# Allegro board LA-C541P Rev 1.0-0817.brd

Outline 356 x 159.9 mm; copper layers: TOP, GND1, IN1, VCC, IN2, IN3, GND2, IN4, GND3, BOTTOM. Coordinates in mm from the lower left corner of the outline.
Outline path: circle c246.25,119.45 r3.5 ; circle c282.95,32.65 r3.5 ; 0,68.4 arc(0.88,70.52) 3,71.4 23.4,71.4 arc(24.11,71.11) 24.4,70.4 24.4,69.4 arc(24.69,68.69) 25.4,68.4 46.5,68.4 arc(47.21,68.69) 47.5,69.4 47.5,70.4 arc(47.79,71.11) 48.5,71.4 52.1,71.4 arc(53.95,71.45) 55.79,71.59 arc(57.34,71.09) 58,69.6 58,69.4 arc(61,66.4) 64,69.4 64,72.03 65.27,73.89 arc(82.27,87.75) 88.07,108.9 arc(88.09,109.65) 88.1,110.4 88.1,123.55 arc(88.25,124.32) 88.69,124.96 95.81,132.09 arc(96.02,132.41) 96.1,132.79 96.1,140.74 arc(96.25,141.51) 96.69,142.16 100.64,146.11 arc(100.96,146.32) 101.34,146.4 102,146.4 arc(102.71,146.69) 103,147.4 arc(103.44,148.46) 104.5,148.9 104.5,157.9 arc(105.09,159.31) 106.5,159.9 117.5,159.9 arc(118.21,159.61) 118.5,158.9 118.5,158.2 arc(118.79,157.49) 119.5,157.2 124.5,157.2 arc(125.21,156.91) 125.5,156.2 125.5,152 arc(132.5,145) 139.5,152 139.5,156.2 arc(139.79,156.91) 140.5,157.2 145.5,157.2 arc(146.21,157.49) 146.5,158.2 146.5,158.9 arc(146.79,159.61) 147.5,159.9 205.5,159.9 arc(206.21,159.61) 206.5,158.9 206.5,158.2 arc(206.79,157.49) 207.5,157.2 212.5,157.2 arc(213.21,156.91) 213.5,156.2 213.5,152 arc(220.5,145) 227.5,152 227.5,156.9 arc(228.09,158.31) 229.5,158.9 230.6,158.9 arc(231.31,158.61) 231.6,157.9 231.6,150.95 arc(231.85,150.7) 232.1,150.95 233.6,150.95 arc(233.81,150.86) 233.9,150.65 233.9,150 arc(233.99,149.79) 234.2,149.7 243.2,149.7 arc(243.41,149.79) 243.5,150 243.5,150.65 arc(243.59,150.86) 243.8,150.95 245.3,150.95 arc(245.55,150.7) 245.8,150.95 245.8,157.9 arc(246.09,158.61) 246.8,158.9 248,158.9 arc(248.71,158.61) 249,157.9 249,152.7 arc(249.29,151.99) 250,151.7 256.8,151.7 arc(257.51,151.41) 257.8,150.7 257.8,136.31 arc(257.89,135.73) 258.14,135.2 259.46,133.2 arc(259.71,132.67) 259.8,132.09 259.8,87 arc(278.6,55.37) 315.37,56.79 318.46,55.11 318.46,51 arc(321.25,49.1) 324.04,51 324.04,59.17 arc(324.19,59.94) 324.63,60.59 328.46,64.41 arc(329.1,64.85) 329.87,65 348,65 arc(349.41,64.41) 350,63 350,51.4 arc(350.29,50.69) 351,50.4 355,50.4 arc(355.71,50.11) 356,49.4 356,14.5 arc(355.12,12.38) 353,11.5 352.5,11.5 arc(351.79,11.21) 351.5,10.5 351.5,5.1 arc(350.62,2.98) 348.5,2.1 270.6,2.1 arc(269.96,1.84) 269.7,1.2 269.7,0.9 arc(269.44,0.26) 268.8,0 244.1,0 arc(243.46,0.26) 243.2,0.9 243.2,1.2 arc(242.94,1.84) 242.3,2.1 39.76,2.1 arc(38.92,2.28) 38.24,2.8 arc(35.2,4.2) 32.16,2.8 arc(31.48,2.28) 30.64,2.1 3,2.1 arc(0.88,2.98) 0,5.1 0,68.4 ; 152.5,154.55 arc(152.59,154.76) 152.8,154.85 154.8,154.85 arc(155.01,154.76) 155.1,154.55 155.1,149.45 arc(155.01,149.24) 154.8,149.15 152.8,149.15 arc(152.59,149.24) 152.5,149.45 152.5,154.55 ; 197.9,154.55 arc(197.99,154.76) 198.2,154.85 200.2,154.85 arc(200.41,154.76) 200.5,154.55 200.5,149.45 arc(200.41,149.24) 200.2,149.15 198.2,149.15 arc(197.99,149.24) 197.9,149.45 197.9,154.55

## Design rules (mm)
net group CLK_PEG_N0: nets CLK_PEG_N0 CLK_PEG_P0
net group CPU_24MHZ_R_D: nets CPU_24MHZ_R_D CPU_24MHZ_R_D#
net group CRT-SYNC_12_20: nets HSYNC_DOCK VSYNC_DOCK
net group CSON_1: nets CSON_1 CSOP_1
net group CSSN_1: nets CSSN_1 CSSP_1
net group CSSN_2: nets CSSN_2 CSSP_2
net group DAT_KBD: nets CLK_KBD DAT_KBD
net group DDR-ALT: nets DDR_A_ALERT# DDR_B_ALERT#
net group DDR_A_CLK2: nets DDR_A_CLK2 DDR_A_CLK#2
net group DDR_A_CLK3: nets DDR_A_CLK3 DDR_A_CLK#3
net group DDR_B_CLK0: nets DDR_B_CLK0 DDR_B_CLK#0
net group DDR_B_CLK1: nets DDR_B_CLK1 DDR_B_CLK#1
net group DIFFPAIR1: nets VCC_IO_SENSE VSS_IO_SENSE
net group DIFFPAIR2: nets VCC_SA_SENSE VSS_SA_SENSE
net group DIFFPAIR3: nets VCC_EDRAM_SENSE VSS_EDRAM_SENSE
net group DIFFPAIR4: nets VCCGTX_SENSE VSSGTX_SENSE
net group DIFFPAIR5: nets VCCGT_SENSE VSSGT_SENSE
net group DIFFPAIR6: nets SW4_DP_N0 SW4_DP_P0
net group DIFFPAIR7: nets USB20_N11_R USB20_P11_R
net group DIFFPAIR8: nets USB20_N9_R USB20_P9_R
net group DIFFPAIR9: nets SW3_DP2_N3_C SW3_DP2_P3_C
net group DIFFPAIR10: nets SW3_DP2_N2_C SW3_DP2_P2_C
net group DIFFPAIR11: nets SW3_DP2_N1_C SW3_DP2_P1_C
net group DIFFPAIR12: nets SW3_DP2_N0_C SW3_DP2_P0_C
net group DIFFPAIR13: nets SW3_DP2_N3 SW3_DP2_P3
net group DIFFPAIR14: nets SW3_DP2_N2 SW3_DP2_P2
net group DIFFPAIR15: nets SW3_DP2_N1 SW3_DP2_P1
net group DIFFPAIR16: nets SW3_DP2_N0 SW3_DP2_P0
net group DIFFPAIR17: nets SW3_DP2_AUXN SW3_DP2_AUXP
net group DIFFPAIR18: nets PCH_DPD_CTRL_CLK PCH_DPD_CTRL_DATA
net group DOCK_DCIN_IS+: nets DOCK_DCIN_IS+ DOCK_DCIN_IS-
net group DOCK_TNY_SMB_DAT: nets DOCK_TNY_SMB_CLK DOCK_TNY_SMB_DAT
net group GND: nets AGND GND_CHASSIS
net group LAN_MDIN0: nets LAN_MDIN0 LAN_MDIP0
net group LAN_MDIN0_L: nets LAN_MDIN0_L LAN_MDIP0_L
net group LAN_MDIN1: nets LAN_MDIN1 LAN_MDIP1
net group LAN_MDIN1_L: nets LAN_MDIN1_L LAN_MDIP1_L
net group LAN_MDIN2: nets LAN_MDIN2 LAN_MDIP2
net group LAN_MDIN2_L: nets LAN_MDIN2_L LAN_MDIP2_L
net group LAN_MDIN3: nets LAN_MDIN3 LAN_MDIP3
net group LAN_MDIN3_L: nets LAN_MDIN3_L LAN_MDIP3_L
net group P81210_VS: nets 81210_VSN 81210_VSP
net group PCH_CPU_BCLK_D: nets PCH_CPU_BCLK_D PCH_CPU_BCLK_D#
net group PCH_CPU_BCLK_R_D: nets PCH_CPU_BCLK_R_D PCH_CPU_BCLK_R_D#
net group PCH_CPU_NSSC_CLK_D: nets PCH_CPU_NSSC_CLK_D PCH_CPU_NSSC_CLK_D#
net group PCH_CPU_PCIBCLK_D: nets PCH_CPU_PCIBCLK_D PCH_CPU_PCIBCLK_D#
net group PCH_CPU_PCIBCLK_R_D: nets PCH_CPU_PCIBCLK_R_D PCH_CPU_PCIBCLK_R_D#
net group PCH_DPB_CTRL_DATA: nets PCH_DPB_CTRL_CLK PCH_DPB_CTRL_DATA
net group PCIE_PTX_C_SW_DRX_N18: nets PCIE_PTX_C_SW_DRX_N18 PCIE_PTX_C_SW_DRX_P18
net group PCIE_PTX_SW_DRX_N18: nets PCIE_PTX_SW_DRX_N18 PCIE_PTX_SW_DRX_P18
net group S5_20: nets REM_DIODE4_N REM_DIODE4_P
net group SENSE_25: nets VCC_SENSE VSS_SENSE
net group SW1_EDP_AUXN: nets SW1_EDP_AUXN SW1_EDP_AUXP
net group SW1_EDP_AUXN_C: nets SW1_EDP_AUXN_C SW1_EDP_AUXP_C
net group SW1_EDP_N0: nets SW1_EDP_N0 SW1_EDP_P0
net group SW1_EDP_N0_C: nets SW1_EDP_N0_C SW1_EDP_P0_C
net group SW1_EDP_N1: nets SW1_EDP_N1 SW1_EDP_P1
net group SW1_EDP_N1_C: nets SW1_EDP_N1_C SW1_EDP_P1_C
net group SW1_EDP_N2: nets SW1_EDP_N2 SW1_EDP_P2
net group SW1_EDP_N2_C: nets SW1_EDP_N2_C SW1_EDP_P2_C
net group SW1_EDP_N3: nets SW1_EDP_N3 SW1_EDP_P3
net group SW1_EDP_N3_C: nets SW1_EDP_N3_C SW1_EDP_P3_C
net group SW1_LAN0_MDIN0: nets SW1_LAN0_MDIN0 SW1_LAN0_MDIP0
net group SW1_LAN0_MDIN1: nets SW1_LAN0_MDIN1 SW1_LAN0_MDIP1
net group SW1_LAN0_MDIN2: nets SW1_LAN0_MDIN2 SW1_LAN0_MDIP2
net group SW1_LAN0_MDIN3: nets SW1_LAN0_MDIN3 SW1_LAN0_MDIP3
net group SW1_LAN1_MDIN0: nets SW1_LAN1_MDIN0 SW1_LAN1_MDIP0
net group SW1_LAN1_MDIN1: nets SW1_LAN1_MDIN1 SW1_LAN1_MDIP1
net group SW1_LAN1_MDIN2: nets SW1_LAN1_MDIN2 SW1_LAN1_MDIP2
net group SW1_LAN1_MDIN3: nets SW1_LAN1_MDIN3 SW1_LAN1_MDIP3
net group SW2_DP_AUXN: nets SW2_DP_AUXN SW2_DP_AUXP
net group SW2_DP_N0: nets SW2_DP_N0 SW2_DP_P0
net group SW2_DP_N0_C: nets SW2_DP_N0_C SW2_DP_P0_C
net group SW2_DP_N0_R: nets SW2_DP_N0_R SW2_DP_P0_R
net group SW2_DP_N1: nets SW2_DP_N1 SW2_DP_P1
net group SW2_DP_N1_C: nets SW2_DP_N1_C SW2_DP_P1_C
net group SW2_DP_N1_R: nets SW2_DP_N1_R SW2_DP_P1_R
net group SW2_DP_N2: nets SW2_DP_N2 SW2_DP_P2
net group SW2_DP_N2_C: nets SW2_DP_N2_C SW2_DP_P2_C
net group SW2_DP_N2_R: nets SW2_DP_N2_R SW2_DP_P2_R
net group SW2_DP_N3: nets SW2_DP_N3 SW2_DP_P3
net group SW2_DP_N3_C: nets SW2_DP_N3_C SW2_DP_P3_C
net group SW2_DP_N3_R: nets SW2_DP_N3_R SW2_DP_P3_R
net group SW3_DP1_AUXN: nets SW3_DP1_AUXN SW3_DP1_AUXP
net group SW3_DP1_N0: nets SW3_DP1_N0 SW3_DP1_P0
net group SW3_DP1_N0_C: nets SW3_DP1_N0_C SW3_DP1_P0_C
net group SW3_DP1_N0_R: nets SW3_DP1_N0_R SW3_DP1_P0_R
net group SW3_DP1_N1: nets SW3_DP1_N1 SW3_DP1_P1
net group SW3_DP1_N1_C: nets SW3_DP1_N1_C SW3_DP1_P1_C
net group SW3_DP1_N1_R: nets SW3_DP1_N1_R SW3_DP1_P1_R
net group SW3_DP1_N2: nets SW3_DP1_N2 SW3_DP1_P2
net group SW3_DP1_N2_C: nets SW3_DP1_N2_C SW3_DP1_P2_C
net group SW3_DP1_N2_R: nets SW3_DP1_N2_R SW3_DP1_P2_R
net group SW3_DP1_N3: nets SW3_DP1_N3 SW3_DP1_P3
net group SW3_DP1_N3_C: nets SW3_DP1_N3_C SW3_DP1_P3_C
net group SW3_DP1_N3_R: nets SW3_DP1_N3_R SW3_DP1_P3_R
net group SW4_DP_AUXN: nets SW4_DP_AUXN SW4_DP_AUXP
net group SW4_DP_N1: nets SW4_DP_N1 SW4_DP_P1
net group SW4_DP_N2: nets SW4_DP_N2 SW4_DP_P2
net group SW4_DP_N3: nets SW4_DP_N3 SW4_DP_P3
net group SW5_DP_AUXN: nets SW5_DP_AUXN SW5_DP_AUXP
net group SW5_DP_N0: nets SW5_DP_N0 SW5_DP_P0
net group SW5_DP_N1: nets SW5_DP_N1 SW5_DP_P1
net group SW5_DP_N2: nets SW5_DP_N2 SW5_DP_P2
net group SW5_DP_N3: nets SW5_DP_N3 SW5_DP_P3
net group UIM_DATA: nets UIM_CLK UIM_DATA
net group UPD_GPU_SMBCLK: nets UPD_GPU_SMBCLK UPD_GPU_SMBDAT
net group USB3_PRX_DTX_N1: nets USB3_PRX_DTX_N1 USB3_PRX_DTX_P1
net group USB3_PRX_DTX_N2: nets USB3_PRX_DTX_N2 USB3_PRX_DTX_P2
net group USB3_PRX_DTX_N3: nets USB3_PRX_DTX_N3 USB3_PRX_DTX_P3
net group USB3_PRX_DTX_N4: nets USB3_PRX_DTX_N4 USB3_PRX_DTX_P4
net group USB3_PRX_DTX_N5: nets USB3_PRX_DTX_N5 USB3_PRX_DTX_P5
net group USB3_PRX_DTX_N6: nets USB3_PRX_DTX_N6 USB3_PRX_DTX_P6
net group USB3_PTX_DRX_N1: nets USB3_PTX_DRX_N1 USB3_PTX_DRX_P1
net group USB3_PTX_DRX_N4: nets USB3_PTX_DRX_N4 USB3_PTX_DRX_P4
net group USB3_PTX_DRX_N5: nets USB3_PTX_DRX_N5 USB3_PTX_DRX_P5
net group USB3_PTX_DRX_N6: nets USB3_PTX_DRX_N6 USB3_PTX_DRX_P6
net group USB20_N1: nets USB20_N1 USB20_P1
net group USB20_N2: nets USB20_N2 USB20_P2
net group USB20_N3: nets USB20_N3 USB20_P3
net group USB20_N4: nets USB20_N4 USB20_P4
net group USB20_N5: nets USB20_N5 USB20_P5
net group USB20_N6: nets USB20_N6 USB20_P6
net group USB20_N7: nets USB20_N7 USB20_P7
net group USB20_N8: nets USB20_N8 USB20_P8
net group USB20_N9: nets USB20_N9 USB20_P9
net group USB20_N10: nets USB20_N10 USB20_P10
net group USB20_N11: nets USB20_N11 USB20_P11
net group ASYN_12: nets CPU_2_PCH_TRIGGER CPU_2_PCH_TRIGGER_R DGPU_HOLD_RST# H_CATERR# H_PM_DOWN H_PM_DOWN_R H_PM_SYNC H_PM_SYNC_R H_PROCHOT# H_PROCHOT#_R H_PWRGD H_THERMTRIP# PCH_2_CPU_TRIGGER PCH_2_CPU_TRIGGER_R PCH_BATLOW# PCH_THERMTRIP#_R PLTRST_CPU# SYS_PWROK_R VCCST_PWRGD_CPU XDP_OBS0_R XDP_OBS1_R
net group ASYN_18: nets H_PECI PCH_PECI PECI_EC_R
net group BC_15: nets BC_CLK_ECE1117 BC_CLK_ECE5048 BC_DAT_ECE1117 BC_DAT_ECE5048
net group CLK: nets AUD_AZACPU_SCLK AUD_AZACPU_SCLK_R CPU_XDP_TCLK DAI_12MHZ# DAI_BCLK# EC_32KHZ_ECE5048 HDA_BIT_CLK HDA_BIT_CLK_R JTAG_CLK PCH_JTAGX SUSCLK SUSCLK_R XCLK_RBIAS
net group CLK-HOST_12: nets PCH_XDP_CLK_DN PCH_XDP_CLK_DN_R PCH_XDP_CLK_DP PCH_XDP_CLK_DP_R
net group CLK-S: nets CLK_PCI_5048 CLK_PCI_DOCK CLK_PCI_LPDEBUG CLK_PCI_MEC PCI_CLK_LPC0 PCI_CLK_LPC1
net group CLK-S_20: nets MEC_XTAL1 MEC_XTAL2 XTAL24_IN_R XTAL24_OUT_R XTAL24_OUT_R1 XTALI XTALO XTALO_R
net group CLK-SRC_12: nets CLK_PCIE_N1 CLK_PCIE_N2 CLK_PCIE_N3 CLK_PCIE_N4 CLK_PCIE_N5 CLK_PCIE_N6 CLK_PCIE_N7 CLK_PCIE_P1 CLK_PCIE_P2 CLK_PCIE_P3 CLK_PCIE_P4 CLK_PCIE_P5 CLK_PCIE_P6 CLK_PCIE_P7
net group CLKREQ: nets CLKREQ_PCIE#1 CLKREQ_PCIE#2 CLKREQ_PCIE#3 CLKREQ_PCIE#4 CLKREQ_PCIE#5 CLKREQ_PCIE#6 CLKREQ_PCIE#7 CLKREQ_PEG#0
net group CLS_10: nets PCH_CL_CLK1 PCH_CL_DATA1 PCH_CL_RST1#
net group COMP: nets CPU_EOPIO_RCOMP DDR_RCOMP0 DDR_RCOMP1 DDR_RCOMP2 EDP_COMP EDRAM_OPIO_RCOMP EDRAM_OPIO_RCOMP_ED2 PCIECOMP PCIECOMP# PEG_COMP USB2_COMP
net group CPU-DDI1: nets CPU_DP1_AUXN CPU_DP1_AUXN_C CPU_DP1_AUXP CPU_DP1_AUXP_C CPU_DP1_N0 CPU_DP1_N0_C CPU_DP1_N1 CPU_DP1_N1_C CPU_DP1_N2 CPU_DP1_N2_C CPU_DP1_N3 CPU_DP1_N3_C CPU_DP1_P0 CPU_DP1_P0_C CPU_DP1_P1 CPU_DP1_P1_C CPU_DP1_P2 CPU_DP1_P2_C CPU_DP1_P3 CPU_DP1_P3_C
net group CPU-DDI2: nets CPU_DP2_AUXN CPU_DP2_AUXN_C CPU_DP2_AUXP CPU_DP2_AUXP_C CPU_DP2_N0 CPU_DP2_N0_C CPU_DP2_N1 CPU_DP2_N1_C CPU_DP2_N2 CPU_DP2_N2_C CPU_DP2_N3 CPU_DP2_N3_C CPU_DP2_P0 CPU_DP2_P0_C CPU_DP2_P1 CPU_DP2_P1_C CPU_DP2_P2 CPU_DP2_P2_C CPU_DP2_P3 CPU_DP2_P3_C
net group CPU-DDI3: nets CPU_DP3_AUXN CPU_DP3_AUXN_C CPU_DP3_AUXP CPU_DP3_AUXP_C CPU_DP3_N0 CPU_DP3_N0_C CPU_DP3_N1 CPU_DP3_N1_C CPU_DP3_N2 CPU_DP3_N2_C CPU_DP3_N3 CPU_DP3_N3_C CPU_DP3_P0 CPU_DP3_P0_C CPU_DP3_P1 CPU_DP3_P1_C CPU_DP3_P2 CPU_DP3_P2_C CPU_DP3_P3 CPU_DP3_P3_C
net group CRITICAL: nets N30357948 PCH_DPWROK PCH_INTRUDER_HDR# PCH_PCIE_WAKE# PCH_PWROK PCH_RSMRST# PCH_RSMRST#_R PM_RSMRST#_AND RESET_OUT# SIO_PWRBTN# SIO_RCIN# SYS_RESET# XDP_DBRESET#
net group CRT-DAC_20_30: nets BLUE_DOCK GREEN_DOCK RED_DOCK
net group DDRA-ADD: nets DDR_A_ACT# DDR_A_BA0 DDR_A_BA1 DDR_A_BG0 DDR_A_BG1 DDR_A_MA0 DDR_A_MA1 DDR_A_MA2 DDR_A_MA3 DDR_A_MA4 DDR_A_MA5 DDR_A_MA6 DDR_A_MA7 DDR_A_MA8 DDR_A_MA9 DDR_A_MA10 DDR_A_MA11 DDR_A_MA12 DDR_A_MA13 DDR_A_MA14 DDR_A_MA15 DDR_A_MA16 DDR_A_PARITY
net group DDRA-CLK: nets DDR_A_CLK0 DDR_A_CLK1 DDR_A_CLK#0 DDR_A_CLK#1
net group DDRA-CTL: nets DDR_A_CKE0 DDR_A_CKE1 DDR_A_CKE2 DDR_A_CKE3 DDR_A_CS#0 DDR_A_CS#1 DDR_A_CS#2 DDR_A_CS#3 DDR_A_ODT0 DDR_A_ODT1 DDR_A_ODT2 DDR_A_ODT3
net group DDRA-D0: nets DDR_A_D0 DDR_A_D1 DDR_A_D2 DDR_A_D3 DDR_A_D4 DDR_A_D5 DDR_A_D6 DDR_A_D7
net group DDRA-D1: nets DDR_A_D8 DDR_A_D9 DDR_A_D10 DDR_A_D11 DDR_A_D12 DDR_A_D13 DDR_A_D14 DDR_A_D15
net group DDRA-D2: nets DDR_A_D16 DDR_A_D17 DDR_A_D18 DDR_A_D19 DDR_A_D20 DDR_A_D21 DDR_A_D22 DDR_A_D23
net group DDRA-D3: nets DDR_A_D24 DDR_A_D25 DDR_A_D26 DDR_A_D27 DDR_A_D28 DDR_A_D29 DDR_A_D30 DDR_A_D31
net group DDRA-D4: nets DDR_A_D32 DDR_A_D33 DDR_A_D34 DDR_A_D35 DDR_A_D36 DDR_A_D37 DDR_A_D38 DDR_A_D39
net group DDRA-D5: nets DDR_A_D40 DDR_A_D41 DDR_A_D42 DDR_A_D43 DDR_A_D44 DDR_A_D45 DDR_A_D46 DDR_A_D47
net group DDRA-D6: nets DDR_A_D48 DDR_A_D49 DDR_A_D50 DDR_A_D51 DDR_A_D52 DDR_A_D53 DDR_A_D54 DDR_A_D55
net group DDRA-D7: nets DDR_A_D56 DDR_A_D57 DDR_A_D58 DDR_A_D59 DDR_A_D60 DDR_A_D61 DDR_A_D62 DDR_A_D63
net group DDRA-DQS: nets DDR_A_DQS0 DDR_A_DQS1 DDR_A_DQS2 DDR_A_DQS3 DDR_A_DQS4 DDR_A_DQS5 DDR_A_DQS6 DDR_A_DQS7 DDR_A_DQS8 DDR_A_DQS#0 DDR_A_DQS#1 DDR_A_DQS#2 DDR_A_DQS#3 DDR_A_DQS#4 DDR_A_DQS#5 DDR_A_DQS#6 DDR_A_DQS#7 DDR_A_DQS#8
net group DDRA-ECC: nets DDR_A_CB0 DDR_A_CB1 DDR_A_CB2 DDR_A_CB3 DDR_A_CB4 DDR_A_CB5 DDR_A_CB6 DDR_A_CB7
net group DDRB-ADD: nets DDR_B_ACT# DDR_B_BA0 DDR_B_BA1 DDR_B_BG0 DDR_B_BG1 DDR_B_MA0 DDR_B_MA1 DDR_B_MA2 DDR_B_MA3 DDR_B_MA4 DDR_B_MA5 DDR_B_MA6 DDR_B_MA7 DDR_B_MA8 DDR_B_MA9 DDR_B_MA10 DDR_B_MA11 DDR_B_MA12 DDR_B_MA13 DDR_B_MA14 DDR_B_MA15 DDR_B_MA16 DDR_B_PARITY
net group DDRB-CLK: nets DDR_B_CLK2 DDR_B_CLK3 DDR_B_CLK#2 DDR_B_CLK#3
net group DDRB-CTL: nets DDR_B_CKE0 DDR_B_CKE1 DDR_B_CKE2 DDR_B_CKE3 DDR_B_CS#0 DDR_B_CS#1 DDR_B_CS#2 DDR_B_CS#3 DDR_B_ODT0 DDR_B_ODT1 DDR_B_ODT2 DDR_B_ODT3
net group DDRB-D1: nets DDR_B_D8 DDR_B_D9 DDR_B_D10 DDR_B_D11 DDR_B_D12 DDR_B_D13 DDR_B_D14 DDR_B_D15
net group DDRB-D2: nets DDR_B_D16 DDR_B_D17 DDR_B_D18 DDR_B_D19 DDR_B_D20 DDR_B_D21 DDR_B_D22 DDR_B_D23
net group DDRB-D3: nets DDR_B_D24 DDR_B_D25 DDR_B_D26 DDR_B_D27 DDR_B_D28 DDR_B_D29 DDR_B_D30 DDR_B_D31
net group DDRB-D4: nets DDR_B_D32 DDR_B_D33 DDR_B_D34 DDR_B_D35 DDR_B_D36 DDR_B_D37 DDR_B_D38 DDR_B_D39
net group DDRB-D5: nets DDR_B_D40 DDR_B_D41 DDR_B_D42 DDR_B_D43 DDR_B_D44 DDR_B_D45 DDR_B_D46 DDR_B_D47
net group DDRB-D6: nets DDR_B_D49 DDR_B_D50 DDR_B_D51 DDR_B_D52 DDR_B_D53 DDR_B_D54 DDR_B_D55
net group DDRB-DQS: nets DDR_B_DQS1 DDR_B_DQS2 DDR_B_DQS3 DDR_B_DQS4 DDR_B_DQS5 DDR_B_DQS6 DDR_B_DQS7 DDR_B_DQS8 DDR_B_DQS#1 DDR_B_DQS#2 DDR_B_DQS#3 DDR_B_DQS#4 DDR_B_DQS#5 DDR_B_DQS#6 DDR_B_DQS#7 DDR_B_DQS#8
net group DDRB-ECC: nets DDR_B_CB0 DDR_B_CB1 DDR_B_CB2 DDR_B_CB3 DDR_B_CB4 DDR_B_CB5 DDR_B_CB6 DDR_B_CB7
net group DMI_12_15: nets DMI_CRX_PTX_N0 DMI_CRX_PTX_N1 DMI_CRX_PTX_N2 DMI_CRX_PTX_N3 DMI_CRX_PTX_P0 DMI_CRX_PTX_P1 DMI_CRX_PTX_P2 DMI_CRX_PTX_P3 DMI_CTX_PRX_N0 DMI_CTX_PRX_N1 DMI_CTX_PRX_N2 DMI_CTX_PRX_N3 DMI_CTX_PRX_P0 DMI_CTX_PRX_P1 DMI_CTX_PRX_P2 DMI_CTX_PRX_P3
net group EDP_12_15: nets EDP_AUXN EDP_AUXN_C EDP_AUXP EDP_AUXP_C EDP_TXN0 EDP_TXN0_C EDP_TXN1 EDP_TXN1_C EDP_TXN2 EDP_TXN2_C EDP_TXN3 EDP_TXN3_C EDP_TXP0 EDP_TXP0_C EDP_TXP1 EDP_TXP1_C EDP_TXP2 EDP_TXP2_C EDP_TXP3 EDP_TXP3_C
net group EMD: nets CFG0 CFG1 CFG2 CFG3 CFG4 CFG5 CFG6 CFG7 CFG8 CFG9 CFG10 CFG11 CFG12 CFG13 CFG14 CFG15 CFG16 CFG17 CFG18 CFG19 CPU_XDP_HOOK6 CPU_XDP_PRDY# CPU_XDP_PREQ# CPU_XDP_TDI CPU_XDP_TDO CPU_XDP_TMS CPU_XDP_TRST# DOCK_POR_RST# IMVP_VR_ON JTAG_RST# ME_RESET# ME_SUS_PWR_ACK PCH_JTAG_TDI PCH_JTAG_TDO PCH_JTAG_TMS PCH_PLTRST# PCH_PLTRST#_EC PLTRST_MMI# PLTRST_USH# POWER_SW#_MB POWER_SW_IN# RUNPWROK SIO_EXT_SMI# SIO_SLP_A# SUSACK# THERMATRIP2# USB_OC0# USB_OC1# USB_OC2# USB_OC3#
net group EMI_15: nets CLK_SIO_14M DMIC0 MEC_XTAL2_R
net group HDA: nets AUD_AZACPU_SDI_R AUD_AZACPU_SDO AUD_AZACPU_SDO_R HDA_RST# HDA_RST#_R HDA_SDIN0 HDA_SDOUT HDA_SDOUT_R HDA_SYNC HDA_SYNC_R
net group LPC: nets LPC_LDRQ1#
net group MDI_LAN: nets RJ45_MDIN0 RJ45_MDIN1 RJ45_MDIN2 RJ45_MDIN3 RJ45_MDIP0 RJ45_MDIP1 RJ45_MDIP2 RJ45_MDIP3
net group MXM-DDIA: nets MXM_DPA_AUXN MXM_DPA_AUXN_C MXM_DPA_AUXP MXM_DPA_AUXP_C MXM_DPA_N0 MXM_DPA_N0_C MXM_DPA_N1 MXM_DPA_N1_C MXM_DPA_N2 MXM_DPA_N2_C MXM_DPA_N3 MXM_DPA_N3_C MXM_DPA_P0 MXM_DPA_P0_C MXM_DPA_P1 MXM_DPA_P1_C MXM_DPA_P2 MXM_DPA_P2_C MXM_DPA_P3 MXM_DPA_P3_C
net group MXM-DDIB: nets MXM_DPB_AUXN MXM_DPB_AUXN_C MXM_DPB_AUXP MXM_DPB_AUXP_C MXM_DPB_N0 MXM_DPB_N0_C MXM_DPB_N1 MXM_DPB_N1_C MXM_DPB_N2 MXM_DPB_N2_C MXM_DPB_N3 MXM_DPB_N3_C MXM_DPB_P0 MXM_DPB_P0_C MXM_DPB_P1 MXM_DPB_P1_C MXM_DPB_P2 MXM_DPB_P2_C MXM_DPB_P3 MXM_DPB_P3_C
net group MXM-DDIC: nets MXM_DPC_AUXN MXM_DPC_AUXN_C MXM_DPC_AUXP MXM_DPC_AUXP_C MXM_DPC_N0 MXM_DPC_N0_C MXM_DPC_N1 MXM_DPC_N1_C MXM_DPC_N2 MXM_DPC_N2_C MXM_DPC_N3 MXM_DPC_N3_C MXM_DPC_P0 MXM_DPC_P0_C MXM_DPC_P1 MXM_DPC_P1_C MXM_DPC_P2 MXM_DPC_P2_C MXM_DPC_P3 MXM_DPC_P3_C
net group MXM-DDID: nets MXM_EDP_AUXN MXM_EDP_AUXN_C MXM_EDP_AUXP MXM_EDP_AUXP_C MXM_EDP_N0 MXM_EDP_N0_C MXM_EDP_N1 MXM_EDP_N1_C MXM_EDP_N2 MXM_EDP_N2_C MXM_EDP_N3 MXM_EDP_N3_C MXM_EDP_P0 MXM_EDP_P0_C MXM_EDP_P1 MXM_EDP_P1_C MXM_EDP_P2 MXM_EDP_P2_C MXM_EDP_P3 MXM_EDP_P3_C
net group PCIE_12: nets PCIE_PRX_C_DTX_N4 PCIE_PRX_C_DTX_N15 PCIE_PRX_C_DTX_N16 PCIE_PRX_C_DTX_P4 PCIE_PRX_C_DTX_P15 PCIE_PRX_C_DTX_P16 PCIE_PRX_C_RD_DTX_N15 PCIE_PRX_C_RD_DTX_N16 PCIE_PRX_C_RD_DTX_P15 PCIE_PRX_C_RD_DTX_P16 PCIE_PRX_DTX_N2 PCIE_PRX_DTX_N3 PCIE_PRX_DTX_N4 PCIE_PRX_DTX_N5 PCIE_PRX_DTX_N6 PCIE_PRX_DTX_N7 PCIE_PRX_DTX_N8 PCIE_PRX_DTX_N9 PCIE_PRX_DTX_N10 PCIE_PRX_DTX_N11 PCIE_PRX_DTX_N12 PCIE_PRX_DTX_N15 PCIE_PRX_DTX_N16 PCIE_PRX_DTX_N17 PCIE_PRX_DTX_N18 PCIE_PRX_DTX_P2 PCIE_PRX_DTX_P3 PCIE_PRX_DTX_P4 PCIE_PRX_DTX_P5 PCIE_PRX_DTX_P6 PCIE_PRX_DTX_P7 PCIE_PRX_DTX_P8 PCIE_PRX_DTX_P9 PCIE_PRX_DTX_P10 PCIE_PRX_DTX_P11 PCIE_PRX_DTX_P12 PCIE_PRX_DTX_P15 PCIE_PRX_DTX_P16 PCIE_PRX_DTX_P17 PCIE_PRX_DTX_P18 PCIE_PRX_RD_DTX_N15 PCIE_PRX_RD_DTX_N16 PCIE_PRX_RD_DTX_P15 PCIE_PRX_RD_DTX_P16 PCIE_PRX_SW_DTX_N18 PCIE_PRX_SW_DTX_P18 PCIE_PTX_C_DRX_N2 PCIE_PTX_C_DRX_N4 PCIE_PTX_C_DRX_N9 PCIE_PTX_C_DRX_N10 PCIE_PTX_C_DRX_N11 PCIE_PTX_C_DRX_N12 PCIE_PTX_C_DRX_N15 PCIE_PTX_C_DRX_N16 PCIE_PTX_C_DRX_N17 PCIE_PTX_C_DRX_N18 PCIE_PTX_C_DRX_P2 PCIE_PTX_C_DRX_P4 PCIE_PTX_C_DRX_P9 PCIE_PTX_C_DRX_P10 PCIE_PTX_C_DRX_P11 PCIE_PTX_C_DRX_P12 PCIE_PTX_C_DRX_P15 PCIE_PTX_C_DRX_P16 PCIE_PTX_C_DRX_P17 PCIE_PTX_C_DRX_P18 PCIE_PTX_C_RD_DRX_N15 PCIE_PTX_C_RD_DRX_N16 PCIE_PTX_C_RD_DRX_P15 PCIE_PTX_C_RD_DRX_P16 PCIE_PTX_DRX_N2 PCIE_PTX_DRX_N3 PCIE_PTX_DRX_N4 PCIE_PTX_DRX_N5 PCIE_PTX_DRX_N6 PCIE_PTX_DRX_N7 PCIE_PTX_DRX_N8 PCIE_PTX_DRX_N9 PCIE_PTX_DRX_N10 PCIE_PTX_DRX_N11 PCIE_PTX_DRX_N12 PCIE_PTX_DRX_N15 PCIE_PTX_DRX_N16 PCIE_PTX_DRX_N17 PCIE_PTX_DRX_N18 PCIE_PTX_DRX_P2 PCIE_PTX_DRX_P3 PCIE_PTX_DRX_P4 PCIE_PTX_DRX_P5 PCIE_PTX_DRX_P6 PCIE_PTX_DRX_P7 PCIE_PTX_DRX_P8 PCIE_PTX_DRX_P9 PCIE_PTX_DRX_P10 PCIE_PTX_DRX_P11 PCIE_PTX_DRX_P12 PCIE_PTX_DRX_P15 PCIE_PTX_DRX_P16 PCIE_PTX_DRX_P17 PCIE_PTX_DRX_P18 PCIE_PTX_RD_DRX_N15 PCIE_PTX_RD_DRX_N16 PCIE_PTX_RD_DRX_P15 PCIE_PTX_RD_DRX_P16
net group PEG_12_15: nets PEG_CRX_C_GTX_N0 PEG_CRX_C_GTX_N1 PEG_CRX_C_GTX_N2 PEG_CRX_C_GTX_N3 PEG_CRX_C_GTX_N4 PEG_CRX_C_GTX_N5 PEG_CRX_C_GTX_N6 PEG_CRX_C_GTX_N7 PEG_CRX_C_GTX_N8 PEG_CRX_C_GTX_N9 PEG_CRX_C_GTX_N10 PEG_CRX_C_GTX_N11 PEG_CRX_C_GTX_N12 PEG_CRX_C_GTX_N13 PEG_CRX_C_GTX_N14 PEG_CRX_C_GTX_N15 PEG_CRX_C_GTX_P0 PEG_CRX_C_GTX_P1 PEG_CRX_C_GTX_P2 PEG_CRX_C_GTX_P3 PEG_CRX_C_GTX_P4 PEG_CRX_C_GTX_P5 PEG_CRX_C_GTX_P6 PEG_CRX_C_GTX_P7 PEG_CRX_C_GTX_P8 PEG_CRX_C_GTX_P9 PEG_CRX_C_GTX_P10 PEG_CRX_C_GTX_P11 PEG_CRX_C_GTX_P12 PEG_CRX_C_GTX_P13 PEG_CRX_C_GTX_P14 PEG_CRX_C_GTX_P15 PEG_CRX_GTX_N0 PEG_CRX_GTX_N1 PEG_CRX_GTX_N2 PEG_CRX_GTX_N3 PEG_CRX_GTX_N4 PEG_CRX_GTX_N5 PEG_CRX_GTX_N6 PEG_CRX_GTX_N7 PEG_CRX_GTX_N8 PEG_CRX_GTX_N9 PEG_CRX_GTX_N10 PEG_CRX_GTX_N11 PEG_CRX_GTX_N12 PEG_CRX_GTX_N13 PEG_CRX_GTX_N14 PEG_CRX_GTX_N15 PEG_CRX_GTX_P0 PEG_CRX_GTX_P1 PEG_CRX_GTX_P2 PEG_CRX_GTX_P3 PEG_CRX_GTX_P4 PEG_CRX_GTX_P5 PEG_CRX_GTX_P6 PEG_CRX_GTX_P7 PEG_CRX_GTX_P8 PEG_CRX_GTX_P9 PEG_CRX_GTX_P10 PEG_CRX_GTX_P11 PEG_CRX_GTX_P12 PEG_CRX_GTX_P13 PEG_CRX_GTX_P14 PEG_CRX_GTX_P15 PEG_CTX_C_GRX_N0 PEG_CTX_C_GRX_N1 PEG_CTX_C_GRX_N2 PEG_CTX_C_GRX_N3 PEG_CTX_C_GRX_N4 PEG_CTX_C_GRX_N5 PEG_CTX_C_GRX_N6 PEG_CTX_C_GRX_N7 PEG_CTX_C_GRX_N8 PEG_CTX_C_GRX_N9 PEG_CTX_C_GRX_N10 PEG_CTX_C_GRX_N11 PEG_CTX_C_GRX_N12 PEG_CTX_C_GRX_N13 PEG_CTX_C_GRX_N14 PEG_CTX_C_GRX_N15 PEG_CTX_C_GRX_P0 PEG_CTX_C_GRX_P1 PEG_CTX_C_GRX_P2 PEG_CTX_C_GRX_P3 PEG_CTX_C_GRX_P4 PEG_CTX_C_GRX_P5 PEG_CTX_C_GRX_P6 PEG_CTX_C_GRX_P7 PEG_CTX_C_GRX_P8 PEG_CTX_C_GRX_P9 PEG_CTX_C_GRX_P10 PEG_CTX_C_GRX_P11 PEG_CTX_C_GRX_P12 PEG_CTX_C_GRX_P13 PEG_CTX_C_GRX_P14 PEG_CTX_C_GRX_P15 PEG_CTX_GRX_N0 PEG_CTX_GRX_N1 PEG_CTX_GRX_N2 PEG_CTX_GRX_N3 PEG_CTX_GRX_N4 PEG_CTX_GRX_N5 PEG_CTX_GRX_N6 PEG_CTX_GRX_N7 PEG_CTX_GRX_N8 PEG_CTX_GRX_N9 PEG_CTX_GRX_N10 PEG_CTX_GRX_N11 PEG_CTX_GRX_N12 PEG_CTX_GRX_N13 PEG_CTX_GRX_N14 PEG_CTX_GRX_N15 PEG_CTX_GRX_P0 PEG_CTX_GRX_P1 PEG_CTX_GRX_P2 PEG_CTX_GRX_P3 PEG_CTX_GRX_P4 PEG_CTX_GRX_P5 PEG_CTX_GRX_P6 PEG_CTX_GRX_P7 PEG_CTX_GRX_P8 PEG_CTX_GRX_P9 PEG_CTX_GRX_P10 PEG_CTX_GRX_P11 PEG_CTX_GRX_P12 PEG_CTX_GRX_P13 PEG_CTX_GRX_P14 PEG_CTX_GRX_P15
net group RTC_15: nets PCH_RTCRST# PCH_RTCX1 PCH_RTCX1_R PCH_RTCX2 SRTCRST#
net group S10: nets DMIC_CLK
net group S12: nets THERMATRIP3#
net group S15: nets PCH_JTAG_TCK
net group S20: nets DDR4_DRAMRST#_PCH DDR_A_DRAMRST# DDR_B_DRAMRST#
net group SATA: nets SATA_PRX_C_DTX_N1 SATA_PRX_C_DTX_P1 SATA_PRX_DTX_N1 SATA_PRX_DTX_P1 SATA_PTX_C_DRX_N1 SATA_PTX_C_DRX_P1 SATA_PTX_DRX_N1 SATA_PTX_DRX_P1
net group SMB_15: nets CHARGER_SMBCLK CHARGER_SMBDAT CLK_DDC2_DOCK CLK_MSE CLK_TP_SIO DAT_DDC2_DOCK DAT_MSE DAT_TP_SIO DDR_XDP_WAN_SMBCLK DDR_XDP_WAN_SMBDAT GPU_SMBCLK_R GPU_SMBDAT_R MEM_SMBCLK MEM_SMBDATA MSCLK MSDATA PBAT_SMBCLK PBAT_SMBDAT PCH_AAC_SMBCLK PCH_AAC_SMBDAT PCH_DPC_CTRL_CLK PCH_DPC_CTRL_DATA SML0_SMBCLK SML0_SMBDATA SML1_SMBCLK SML1_SMBDATA USH_SMBCLK USH_SMBDAT
net group SPI: nets PCH_SPI_CS#0 PCH_SPI_CS#0_R1 PCH_SPI_CS#0_R2 PCH_SPI_CS#1 PCH_SPI_CS#1_R1 PCH_SPI_CS#1_R2 PCH_SPI_CS#2 PCH_SPI_CS#2_R PCH_SPI_D0 PCH_SPI_D0_0_R PCH_SPI_D0_1_R PCH_SPI_D0_R1 PCH_SPI_D1 PCH_SPI_D1_0_R PCH_SPI_D1_1_R PCH_SPI_D1_R1 PCH_SPI_D2 PCH_SPI_D2_0_R PCH_SPI_D2_1_R PCH_SPI_D2_R1 PCH_SPI_D2_XDP PCH_SPI_D3 PCH_SPI_D3_0_R PCH_SPI_D3_1_R PCH_SPI_D3_R1 SPI_DINTPM SPI_DOTPM
net group SPI_CLK: nets PCH_SPI_CLK PCH_SPI_CLK_0_R PCH_SPI_CLK_1_R PCH_SPI_CLK_R1 SPI_CLKTPM
net group SVID_15: nets CPU_VIDALERT# VR_SVID_ALERT# VR_SVID_CLK VR_SVID_DATA
net group THERMAL: nets REM_DIODE1_N REM_DIODE1_P REM_DIODE2_N REM_DIODE2_P REM_DIODE3_N REM_DIODE3_P
net group UIM: nets UIM_RESET
net group USB3_PTX_DRX_N3: nets USB3_PTX_DRX_P3
net group USB30_12: nets USB3_PTX_C_DRX_N2 USB3_PTX_C_DRX_P2 USB3_PTX_DRX_N2 USB3_PTX_DRX_N3 USB3_PTX_DRX_P2
nets with their own width: min track width 0.254; nets +DC_IN_SS +DOCK_PWR_BAR +VBUS_DC_SS SATA_SIDE_LED
nets with their own width: min track width 0.508; nets +0.6V_DDR_VTT +0.6V_P +0.9V_LAN +1.0V_AAZPLL +1.0V_AMPHYPLL +1.0V_APLLEBB +1.0V_AUSB +1.0V_CLK1 +1.0V_CLK2 +1.0V_CLK3 +1.0V_CLK4 +1.0V_CLK5 +1.0V_DSW +1.0V_DTS +1.0V_DUSB +1.0V_MPHY +1.0V_PRIM +1.0V_PRIM_XDP +1.0V_VCCSFR +1.0V_VCCST +1.0V_VCCSTG +1.2V_MEM +1.2V_MEN_P +1.8V_ALW +1.8V_ALW_PCHRES +1.8V_RUN +1.8V_RUN_EDRAM +1.8V_RUN_EDRAM_ED2 +1.8VSP +1.8VSP_ON +1VSP_B+ +2.5V_MEM +2.5V_MEMP +2.8V_FHV +3.3V_1.8V_AZIO +3.3V_1.8V_FUSE +3.3V_1.8V_GPPA +3.3V_1.8V_GPPD +3.3V_1.8V_SPI +3.3V_ALW +3.3V_ALW2 +3.3V_ALW_PCH +3.3V_ALW_PCH_PWR +3.3V_ALW_PCHRES +3.3V_ALW_U46 +3.3V_ALW_U51 +3.3V_HDD +3.3V_HDD1 +3.3V_LAN +3.3V_LAN_OUT +3.3V_LAN_PWR +3.3V_M +3.3V_M_PWR +3.3V_M_TPM +3.3V_MXM +3.3V_MXM_PWR +3.3V_PGPPBCH +3.3V_PGPPEF +3.3V_PGPPG +3.3V_PHVC +3.3V_PRTC +3.3V_PRTCPRIM +3.3V_PUSBDSW +3.3V_RTC_LDO +3.3V_RUN +3.3V_RUN_DIMM1 +3.3V_RUN_DIMM2 +3.3V_RUN_DIMM3 +3.3V_RUN_DIMM4 +3.3V_RUN_PWR +3.3V_SPI +3.3V_SSD1 +3.3V_TP +3.3V_VTR +3.3V_WLAN +3.3V_WLAN_PWR +3.3V_WWAN +3VALWP +5V_ALW +5V_ALW2 +5V_HDD +5V_MXM +5V_MXM_PWR +5V_RUN +5V_RUN_PWR +5VALWP +CAMERA_VDD +CAP_LDO +COINCELL +DC_IN +DCIN +DCIN_JACK +DDR_VREF_B_DQ +DDR_VREF_CA +LOM_VCT +MXM_PWR +NBDOCK_DC_IN_SS +PECI_VREF +REGCTL_PNP10 +RSVD_VCC3P3_2 +RTC_CELL +RTC_CELL_VBAT +SDC_IN +SIM_PWR +TRM_CT1 +TRM_CT2 +TRM_CT3 +TRM_CT4 +V0.95SP_B+ +V_DDR_REFCA_A +V_DDR_REFCA_B +VCC_CORE +VCC_EDRAM +VCC_EDRAM_ED2 +VCC_EDRAM_FUSEPRG +VCC_EDRAM_FUSEPRG_ED2 +VCC_EDRAM_P +VCC_EOPIO +VCC_EOPIO_ED2 +VCC_GT +VCC_GTU +VCC_IO +VCC_SA +VCC_SFR_OC +VCC_VDDQ_CLK +VCCAUSB_VCCAAZPLL_1P0 +VCHGR +VR_CAP +VTR_ADC BAT1_LED# BAT2_LED# BATT_WHITE_LED BATT_YELLOW_LED GND GNDA_CHG
nets with their own width: min track width 1.016; nets +BL_PWR_SRC +CHAGER_SRC +DC1_PWR_SRC +LCDVDD +MXM_PWR_SRC +MXM_SRC_EN# +PWR_SRC +PWR_SRC_MXM

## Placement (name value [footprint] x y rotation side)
C1  0.1U_0603_25V7K  [C_0603]  222.04 95.78 180 top
C2  10U_0805_25VAK  [C_0805]  227.77 93.43 0 top
C3  680P_0603_50V7K  [C_0603]  222.59 77.49 270 top
C4  68P_0402_50V8J  [C_0402]  219.43 90.44 180 top
C5  10U_0603_6.3V6M  [C_0603]  32.74 21.86 0 top
C6  0.1U_0402_10V6K  [C_0402]  288.9 4.4 180 top
C7  .1U_0402_16V7K  [C_0402]  212.15 90.46 180 top
C8  0.1U_0402_10V6K  [C_0402]  148.57 71.64 90 top
C30  10U_0805_10V6K  [C_0805]  99.04 96.2 90 top
C31  0.1U_0402_25V6  [C_0402]  240.71 84.81 270 top
C32  1U_0402_6.3V6K  [C_0402]  241.69 84.81 270 top
C33  0.1U_0402_25V6  [C_0402]  242.71 84.81 270 top
C34  1U_0402_6.3V6K  [C_0402]  243.72 84.81 270 top
C35  1U_0402_6.3V6K  [C_0402]  240.77 88.41 180 top
C36  1U_0402_6.3V6K  [C_0402]  253.6 85.31 270 top
C90  0.1U_0402_10V7K  [C_0402]  176.07 72.71 90 top
C92  0.1U_0402_10V7K  [C_0402]  215.97 74.95 0 top
C94  0.1U_0402_10V7K  [C_0402]  142.37 73.93 0 top
C97  2.2U_0402_6.3V6M  [C_0402]  181.08 138.18 90 top
C98  2.2U_0402_6.3V6M  [C_0402]  148.9 141.84 0 top
C99  2.2U_0402_6.3V6M  [C_0402]  148.39 102.26 180 top
C100  2.2U_0402_6.3V6M  [C_0402]  165.33 92.53 180 top
C141  3300P_0402_25V7K  [C_0402]  249.93 84.59 0 top
C143  1500P_0402_50V7K  [C_0402]  249.07 85.48 180 top
C248  0.1U_0402_10V7K  [C_0402]  106.81 157.51 0 bottom
C249  0.1U_0603_50V7K  [C_0603]  111.23 140.1 180 bottom
C272  100P_0402_50V8J  [C_0402]  104.63 35.08 270 top
C273  100P_0402_50V8J  [C_0402]  182.38 44.82 270 bottom
C288  100P_0402_50V8J  [C_0402]  332.13 26.12 0 bottom
C291  100P_0402_50V8J  [C_0402]  209.47 106.2 270 top
C292  47P_0402_50V8J  [C_0402]  195.38 118.65 90 bottom
C293  0.01U_0402_50V7K  [C_0402]  111.47 135.31 90 bottom
C296  0.1U_0603_50V7K  [C_0603]  108.87 140.08 180 bottom
C297  1U_1206_50V7  [C_1206]  107.66 134.93 0 bottom
C298  0.1U_0402_25V6  [C_0402]  119.93 138.27 270 bottom
C299  0.1U_0402_25V6  [C_0402]  100.59 135 180 bottom
C300  10U_0603_6.3V6M  [C_0603]  100.59 136.14 180 bottom
C301  0.1U_0402_25V6  [C_0402]  97.92 130.55 180 bottom
C310  0.1U_0402_25V6  [C_0402]  141.2 132.67 0 top
C320  0.1U_0402_25V6  [C_0402]  206.99 99.16 270 bottom
C327  0.1U_0402_25V6  [C_0402]  198.78 96.03 0 bottom
C328  10U_0805_6.3V6M  [C_0805]  212.42 87.9 0 bottom
C330  10U_0603_6.3V6M  [C_0603]  280.78 44.91 270 top
C332  10U_0603_6.3V6M  [C_0603]  143.74 71.08 90 top
C339  100P_0402_50V8J  [C_0402]  242.47 69.1 90 bottom
C340  100P_0402_50V8J  [C_0402]  31.37 24.43 270 bottom
C357  10U_0603_6.3V6M  [C_0603]  207.83 96.2 270 top
C364  0.1U_0402_25V6  [C_0402]  97.71 96.21 90 top
C365  2.2U_0402_6.3V6M  [C_0402]  251.69 84.61 270 top
C366  0.1U_0402_10V7K  [C_0402]  156.25 145.5 180 top
C367  0.1U_0402_10V7K  [C_0402]  156.25 144.61 180 top
C368  0.1U_0402_10V7K  [C_0402]  160.93 146.65 270 top
C369  0.1U_0402_10V7K  [C_0402]  161.82 146.65 270 top
C370  0.1U_0402_25V6  [C_0402]  281.86 44.55 270 top
C371  0.1U_0402_10V6K  [C_0402]  111.98 156.36 0 top
C372  0.1U_0402_10V6K  [C_0402]  107.66 155.21 0 top
C373  0.1U_0402_10V6K  [C_0402]  111.98 155.47 0 top
C374  0.1U_0402_10V6K  [C_0402]  107.66 156.1 0 top
C375  0.1U_0402_10V6K  [C_0402]  107.66 153.44 0 top
C376  0.1U_0402_10V6K  [C_0402]  107.66 154.33 0 top
C377  0.1U_0402_10V6K  [C_0402]  110.28 151.16 270 top
C378  0.1U_0402_10V6K  [C_0402]  111.17 151.16 270 top
C379  0.1U_0402_10V6K  [C_0402]  109.07 149.26 270 top
C380  0.1U_0402_10V6K  [C_0402]  109.96 149.26 270 top
C391  0.1U_0402_25V6  [C_0402]  5.43 40.11 0 top
C392  10U_0603_6.3V6M  [C_0603]  6.39 50.12 180 top
C395  1000P_0402_50V7K  [C_0402]  31.79 22.05 180 top
C396  10U_0603_6.3V6M  [C_0603]  118.29 143.02 90 bottom
C400  10U_0603_6.3V6M  [C_0603]  16.47 44.22 180 top
C401  0.1U_0402_25V6  [C_0402]  6.41 51.26 180 top
C403  22U_0603_6.3V6M  [C_0603]  28.21 19.93 180 top
C404  0.1U_0402_25V6  [C_0402]  28.44 18.82 180 top
C406  0.1U_0402_25V6  [C_0402]  31.79 21.1 180 top
C424  0.1U_0402_10V7K  [C_0402]  162.71 146.65 270 top
C425  0.1U_0402_10V7K  [C_0402]  163.6 146.65 270 top
C426  0.1U_0402_10V7K  [C_0402]  164.49 146.65 270 top
C427  0.1U_0402_10V7K  [C_0402]  165.38 146.65 270 top
C431  0.1U_0402_10V7K  [C_0402]  159.28 154.59 270 top
C436  470P_0402_50V7K  [C_0402]  225.01 122.45 180 top
C437  470P_0402_50V7K  [C_0402]  213.03 99.51 270 top
C438  0.1U_0402_10V7K  [C_0402]  160.17 154.59 270 top
C439  0.1U_0402_10V7K  [C_0402]  161.06 154.59 270 top
C440  0.1U_0402_10V7K  [C_0402]  161.95 154.59 270 top
C441  0.1U_0402_10V7K  [C_0402]  162.84 154.59 270 top
C442  0.1U_0402_10V7K  [C_0402]  163.73 154.59 270 top
C443  0.1U_0402_10V7K  [C_0402]  164.68 152.05 270 top
C444  0.1U_0402_10V7K  [C_0402]  165.57 152.05 270 top
C450  10U_0603_6.3V6M  [C_0603]  301.84 31.68 180 top
C458  0.1U_0402_10V7K  [C_0402]  255.94 107.53 0 top
C459  0.1U_0402_10V7K  [C_0402]  255.94 108.42 0 top
C460  0.1U_0402_10V7K  [C_0402]  256.86 109.43 180 top
C461  0.1U_0402_10V7K  [C_0402]  256.86 110.32 180 top
C462  10U_0603_6.3V6M  [C_0603]  243.95 110.64 90 top
C463  0.1U_0402_10V7K  [C_0402]  245.03 110.56 90 top
C464  1U_0603_10V7K  [C_0603]  252.65 114.7 0 top
C466  0.1U_0402_10V7K  [C_0402]  255.93 111.27 0 top
C467  0.1U_0402_10V7K  [C_0402]  245.98 110.56 90 top
C468  0.1U_0402_10V7K  [C_0402]  255.94 112.23 0 top
C469  0.1U_0402_10V7K  [C_0402]  254.99 105.51 270 top
C470  22P_0402_50V8J  [C_0402]  252.25 117.24 0 top
C471  27P_0402_50V8J  [C_0402]  251.39 117.24 180 top
C472  0.1U_0402_25V6  [C_0402]  239.79 120.42 90 top
C473  0.1U_0402_25V6  [C_0402]  230.36 115.41 270 top
C474  0.1U_0402_25V6  [C_0402]  229.39 122.32 0 top
C477  470P_0402_50V7K  [C_0402]  18.04 46.15 270 top
C478  0.1U_0402_10V7K  [C_0402]  229.47 115.41 270 top
C479  0.47U_0603_10V7K  [C_0603]  240.88 123.75 180 top
C480  0.47U_0603_10V7K  [C_0603]  241.9 123.75 0 top
C481  1U_0603_10V6K  [C_0603]  226.7 142.18 180 top
C483  0.1U_0402_10V7K  [C_0402]  226.71 144.28 180 top
C484  0.47U_0603_10V7K  [C_0603]  253.72 122.26 0 top
C485  150P_1808_2.5KV8J  [C_1808]  255.88 127.77 90 top
C486  0.47U_0603_10V7K  [C_0603]  253.72 123.53 0 top
C494  0.1U_0402_10V6K  [C_0402]  173.51 135.08 0 top
C495  0.1U_0402_10V6K  [C_0402]  173.54 136.5 0 top
C496  0.1U_0402_10V6K  [C_0402]  151.58 95.57 270 top
C497  0.1U_0402_10V6K  [C_0402]  150.12 94.66 90 top
C499  0.1U_0402_10V6K  [C_0402]  175.71 138.99 270 top
C500  0.1U_0402_10V6K  [C_0402]  143.54 138.39 0 top
C501  0.1U_0402_10V6K  [C_0402]  143.56 139.37 0 top
C502  0.1U_0402_10V6K  [C_0402]  144.18 142.01 270 top
C503  0.1U_0402_10V6K  [C_0402]  147.63 96.83 0 top
C504  0.1U_0402_10V6K  [C_0402]  182.94 134.51 180 top
C505  0.1U_0402_10V6K  [C_0402]  151.83 103.95 270 top
C506  0.1U_0402_10V6K  [C_0402]  163.71 93.47 0 top
C507  0.1U_0402_10V6K  [C_0402]  170.85 91.96 90 top
C508  0.1U_0402_10V6K  [C_0402]  174.72 97.56 0 bottom
C509  0.1U_0402_10V6K  [C_0402]  174.65 94.76 0 bottom
C513  10U_0603_6.3V6M  [C_0603]  149.08 121.75 180 top
C514  10U_0805_10V6K  [C_0805]  301.68 28.28 180 top
C523  0.1U_0402_10V6K  [C_0402]  184.35 130.01 90 bottom
C524  0.1U_0402_10V6K  [C_0402]  182.51 130.01 90 bottom
C525  0.1U_0402_10V6K  [C_0402]  183.46 130.01 90 bottom
C526  0.1U_0402_10V6K  [C_0402]  180.66 130.01 90 bottom
C527  0.1U_0402_10V6K  [C_0402]  181.62 130.01 90 bottom
C528  0.1U_0402_10V6K  [C_0402]  177.93 130.01 90 bottom
C529  0.1U_0402_10V6K  [C_0402]  179.78 130.01 90 bottom
C530  0.1U_0402_10V6K  [C_0402]  178.82 130.01 90 bottom
C531  0.1U_0402_10V6K  [C_0402]  170.43 136.18 0 bottom
C532  0.1U_0402_10V6K  [C_0402]  170.43 137.07 0 bottom
C535  0.1U_0402_10V6K  [C_0402]  158.13 93.97 180 bottom
C536  10U_0603_6.3V6M  [C_0603]  219.1 124.48 90 top
C537  0.1U_0402_10V6K  [C_0402]  147.51 130.05 90 bottom
C538  470P_0402_50V7K  [C_0402]  225.01 123.34 180 top
C539  470P_0402_50V7K  [C_0402]  243.13 77.87 180 top
C540  0.1U_0402_10V6K  [C_0402]  159.79 109.64 90 bottom
C541  470P_0402_50V7K  [C_0402]  321.72 32.02 90 top
C542  470P_0402_50V7K  [C_0402]  214.1 97.18 180 top
C543  470P_0402_50V7K  [C_0402]  300.56 29.61 0 top
C544  1000P_0402_50V7K  [C_0402]  300.56 30.5 0 top
C545  0.1U_0402_10V6K  [C_0402]  160.68 109.64 90 bottom
C546  0.1U_0402_10V6K  [C_0402]  158.13 94.86 180 bottom
C547  470P_0402_50V7K  [C_0402]  147.3 122.88 0 top
C548  0.1U_0402_10V6K  [C_0402]  158.14 92.76 180 bottom
C549  0.1U_0402_10V6K  [C_0402]  148.4 130.05 90 bottom
C550  0.1U_0402_10V6K  [C_0402]  157.89 109.64 90 bottom
C551  0.1U_0402_10V6K  [C_0402]  158.78 109.64 90 bottom
C552  0.1U_0402_10V6K  [C_0402]  158.14 91.87 180 bottom
C553  0.1U_0402_10V6K  [C_0402]  155.98 109.64 90 bottom
C554  0.1U_0402_10V6K  [C_0402]  152.86 137.53 180 top
C555  0.1U_0402_10V6K  [C_0402]  142.08 132.49 90 bottom
C556  0.1U_0402_10V6K  [C_0402]  146.18 128.28 90 bottom
C557  0.1U_0402_10V6K  [C_0402]  147.07 128.28 90 bottom
C558  0.1U_0402_10V6K  [C_0402]  141.19 132.49 90 bottom
C559  0.1U_0402_10V6K  [C_0402]  144.85 130.05 90 bottom
C560  0.1U_0402_10V6K  [C_0402]  145.73 130.05 90 bottom
C561  0.1U_0402_10V6K  [C_0402]  153.86 130.05 90 bottom
C562  0.1U_0402_10V6K  [C_0402]  143.51 128.28 90 bottom
C563  0.1U_0402_10V6K  [C_0402]  152.97 130.05 90 bottom
C564  0.1U_0402_10V6K  [C_0402]  144.4 128.28 90 bottom
C565  0.1U_0402_10V6K  [C_0402]  152.53 128.28 90 bottom
C566  0.1U_0402_10V6K  [C_0402]  139.07 130.41 90 bottom
C567  0.1U_0402_10V6K  [C_0402]  151.64 128.28 90 bottom
C568  0.1U_0402_10V6K  [C_0402]  140.11 130.41 90 bottom
C569  0.1U_0402_10V6K  [C_0402]  151.07 130.05 90 bottom
C570  0.1U_0402_10V6K  [C_0402]  149.73 128.28 90 bottom
C571  0.1U_0402_10V6K  [C_0402]  150.18 130.05 90 bottom
C572  0.1U_0402_10V6K  [C_0402]  148.85 128.28 90 bottom
C573  0.1U_0402_10V6K  [C_0402]  156.87 109.64 90 bottom
C574  0.1U_0402_10V6K  [C_0402]  156.36 98.86 180 bottom
C575  0.1U_0402_10V6K  [C_0402]  154.08 109.64 90 bottom
C576  0.1U_0402_10V6K  [C_0402]  156.36 97.97 180 bottom
C577  0.1U_0402_10V6K  [C_0402]  154.97 109.64 90 bottom
C578  0.1U_0402_10V6K  [C_0402]  158.13 97.53 180 bottom
C580  0.1U_0402_10V6K  [C_0402]  158.13 96.64 180 bottom
C581  0.1U_0402_10V6K  [C_0402]  156.36 96.19 180 bottom
C583  0.1U_0402_10V6K  [C_0402]  156.36 95.3 180 bottom
C584  0.1U_0402_10V6K  [C_0402]  170.57 130.01 90 bottom
C585  0.1U_0402_10V6K  [C_0402]  164.76 101.77 270 bottom
C586  0.1U_0402_10V6K  [C_0402]  171.46 130.01 90 bottom
C587  0.1U_0402_10V6K  [C_0402]  163.87 101.77 270 bottom
C588  0.1U_0402_10V6K  [C_0402]  170.43 138.02 0 bottom
C589  0.1U_0402_10V6K  [C_0402]  166.01 99.96 270 bottom
C590  0.1U_0402_10V6K  [C_0402]  165.12 99.96 270 bottom
C591  0.1U_0402_10V6K  [C_0402]  170.43 138.91 0 bottom
C592  0.1U_0402_10V6K  [C_0402]  167.3 101.9 270 bottom
C593  0.1U_0402_10V6K  [C_0402]  176.98 130.01 90 bottom
C594  0.1U_0402_10V6K  [C_0402]  166.41 101.9 270 bottom
C595  0.1U_0402_10V6K  [C_0402]  168.55 100.08 270 bottom
C596  0.1U_0402_10V6K  [C_0402]  167.66 100.08 270 bottom
C597  0.1U_0402_10V6K  [C_0402]  176.09 130.01 90 bottom
C598  0.1U_0402_10V6K  [C_0402]  175.14 130.01 90 bottom
C601  0.1U_0402_10V6K  [C_0402]  174.69 95.69 0 bottom
C603  0.1U_0402_25V6  [C_0402]  220.7 109.88 180 top
C604  0.047U_0402_16V4Z  [C_0402]  220.7 110.77 180 top
C605  0.047U_0402_16V4Z  [C_0402]  220.7 111.66 180 top
C606  0.1U_0402_25V6  [C_0402]  219.62 127.87 0 top
C607  0.1U_0402_25V6  [C_0402]  219.62 128.76 0 top
C608  4.7U_0603_6.3V6K  [C_0603]  221.03 129.84 180 top
C610  0.047U_0402_16V4Z  [C_0402]  321.3 41.39 180 top
C611  0.047U_0402_16V4Z  [C_0402]  321.3 40.5 180 top
C612  33P_0402_50V8J  [C_0402]  323.1 24.85 0 top
C613  22U_0603_6.3V6M  [C_0603]  321.59 39.45 180 top
C614  33P_0402_50V8J  [C_0402]  323.1 23.96 0 top
C615  330U_D2E_6.3VM_R25M  [C_D2E]  327.51 28.75 0 top
C617  33P_0402_50V8J  [C_0402]  3.47 12.09 270 top
C618  33P_0402_50V8J  [C_0402]  6.01 12.09 270 top
C619  330U_D2E_6.3VM_R25M  [C_D2E]  18.39 11 270 top
C621  0.047U_0402_16V4Z  [C_0402]  6.9 12.09 270 top
C622  22U_0805_6.3VAM  [C_0805]  22.33 12.77 0 top
C623  0.047U_0402_16V4Z  [C_0402]  22.38 11.35 0 top
C626  0.1U_0402_10V6K  [C_0402]  174.25 130.01 90 bottom
C627  0.1U_0402_10V6K  [C_0402]  174.69 96.58 0 bottom
C628  0.1U_0402_10V6K  [C_0402]  173.3 130.01 90 bottom
C629  0.1U_0402_10V6K  [C_0402]  172.41 130.01 90 bottom
C695  0.033U_0402_16V7K  [C_0402]  167.41 148.43 270 top
C696  0.033U_0402_16V7K  [C_0402]  166.84 155.46 90 top
C697  0.01U_0402_16V7K  [C_0402]  172.24 152.73 90 top
C698  0.01U_0402_16V7K  [C_0402]  173.13 152.73 90 top
C699  0.01U_0402_16V7K  [C_0402]  173.13 156.43 270 top
C700  0.01U_0402_16V7K  [C_0402]  174.02 156.43 270 top
C701  1U_0402_6.3V6K  [C_0402]  189.44 156.29 270 top
C702  0.1U_0603_50V7K  [C_0603]  157.44 155.6 90 top
C703  0.1U_0603_50V7K  [C_0603]  192.87 153.75 180 top
C704  12P_0402_50V8J  [C_0402]  190.65 148.43 270 top
C708  0.1U_0402_10V7K  [C_0402]  177.62 115.37 90 top
C709  0.1U_0402_25V6  [C_0402]  183.79 115.28 90 top
C710  0.1U_0402_25V6  [C_0402]  183.83 108.78 0 top
C713  4.7P_0402_50V8C  [C_0402]  183.8 107.84 0 top
C714  4.7U_0603_6.3V6K  [C_0603]  177.62 106.43 0 top
C716  0.047U_0402_16V4Z  [C_0402]  173.94 106.56 270 top
C717  0.1U_0402_10V7K  [C_0402]  178.18 105.35 0 top
C718  0.1U_0402_10V7K  [C_0402]  173.79 109.48 0 top
C719  0.1U_0402_10V7K  [C_0402]  187.61 116.48 0 bottom
C721  0.1U_0402_10V6K  [C_0402]  309.21 24.61 270 top
C722  0.1U_0402_10V6K  [C_0402]  309.21 30.58 270 top
C723  0.1U_0402_10V6K  [C_0402]  308.95 34.81 90 top
C724  0.1U_0402_10V6K  [C_0402]  58.62 32.41 0 top
C725  0.1U_0402_10V6K  [C_0402]  49.95 35.64 180 top
C726  0.1U_0402_10V6K  [C_0402]  49.5 33.23 180 top
C733  1U_0402_6.3V6K  [C_0402]  209.77 121.26 90 bottom
C734  1U_0402_6.3V6K  [C_0402]  207.98 122.16 0 bottom
C735  1U_0402_6.3V6K  [C_0402]  191.79 118.67 0 bottom
C736  0.1U_0402_25V6  [C_0402]  200.95 118.65 90 bottom
C737  0.1U_0402_25V6  [C_0402]  204.06 103.14 0 bottom
C739  0.1U_0402_25V6  [C_0402]  201.38 103.68 270 bottom
C740  0.1U_0402_25V6  [C_0402]  197.39 118.65 90 bottom
C741  33P_0402_50V8J  [C_0402]  204.5 119.51 270 bottom
C743  33P_0402_50V8J  [C_0402]  202.74 119.49 180 bottom
C744  4700P_0402_25V7K  [C_0402]  210.05 111.05 0 bottom
C746  0.1U_0402_25V6  [C_0402]  171.48 121.01 270 bottom
C747  4.7P_0402_50V8C  [C_0402]  198.01 102.86 0 bottom
C757  1U_0402_6.3V6K  [C_0402]  200.06 118.65 90 bottom
C759  100P_0402_50V8J  [C_0402]  210.29 152.03 90 bottom
C762  10U_0603_6.3V6M  [C_0603]  327.97 36.67 0 top
C763  0.1U_0402_10V6K  [C_0402]  317.58 22.5 0 top
C764  10U_0603_6.3V6M  [C_0603]  212.62 96.1 0 top
C766  0.1U_0402_10V6K  [C_0402]  58.69 36.47 0 top
C767  10U_0603_6.3V6M  [C_0603]  242.72 81.87 180 top
C774  0.01U_0402_50V7K  [C_0402]  225.08 105.68 180 top
C776  10U_1206_25V6M  [C_1206]  227.29 95.33 0 top
C777  0.1U_0402_25V6  [C_0402]  199.8 103.76 270 bottom
C778  0.1U_0402_25V6  [C_0402]  308 9.72 90 top
C779  4.7U_0603_6.3V6K  [C_0603]  202.54 110.13 90 top
C780  0.1U_0402_25V6  [C_0402]  195.42 104.07 270 bottom
C781  0.1U_0402_25V6  [C_0402]  193.05 110.37 180 bottom
C782  10U_0603_6.3V6M  [C_0603]  194.34 104.06 270 bottom
C783  4.7U_0603_6.3V6K  [C_0603]  182.19 138.91 270 top
C784  4.7U_0603_6.3V6K  [C_0603]  152.27 143.68 0 top
C785  4.7U_0603_6.3V6K  [C_0603]  147.45 103.3 0 top
C786  4.7U_0603_6.3V6K  [C_0603]  164.2 94.76 0 top
C787  0.1U_0402_25V6  [C_0402]  319.83 6.7 270 top
C1167  470P_0402_50V7K  [C_0402]  226.71 143.32 180 top
C1176  330U_D2E_6.3VM_R25M  [C_D2E]  327.54 33.52 0 top
C1177  22U_0805_6.3V6M  [C_0805]  256.4 106.41 270 top
C1178  22U_0805_6.3V6M  [C_0805]  226.36 119.76 90 top
C1216  0.1U_0402_25V6  [C_0402]  180.18 120.95 270 bottom
C1343  2200P_0402_50V7K  [C_0402]  213.77 107.02 0 bottom
C1344  0.01U_0402_16V7K  [C_0402]  151.63 121.56 180 bottom
C1345  0.1U_0402_25V6  [C_0402]  198.27 119.56 0 bottom
C1346  2200P_0402_50V7K  [C_0402]  207.12 104 180 bottom
C1348  0.1U_0402_25V6  [C_0402]  207.98 115.94 0 bottom
C1349  1U_0402_6.3V6K  [C_0402]  202.27 103.68 270 bottom
C1350  2200P_0402_50V7K  [C_0402]  207.99 105.26 90 bottom
C1351  2200P_0402_50V7K  [C_0402]  208.9 104 180 bottom
C1352  1U_0402_6.3V6K  [C_0402]  208.88 117.73 270 bottom
C1353  0.1U_0402_25V6  [C_0402]  207.99 117.73 270 bottom
C1354  1U_0402_6.3V6K  [C_0402]  209.77 117.73 270 bottom
C1355  0.1U_0402_25V6  [C_0402]  207.96 109.55 0 bottom
C1356  1U_0402_6.3V6K  [C_0402]  335.89 19.27 270 bottom
C1402  330U_D2E_6.3VM_R25M  [C_D2E]  215.32 137.34 180 bottom
C1410  0.1U_0402_25V6  [C_0402]  289.79 31.08 270 top
C1411  0.1U_0402_25V6  [C_0402]  296.84 27.91 270 top
C1414  0.1U_0402_25V6  [C_0402]  289.81 29.29 180 top
C1418  0.1U_0402_10V7K  [C_0402]  254.41 118.51 0 top
C1420  2.2U_0402_6.3V6M  [C_0402]  249.06 82.8 90 top
C1421  0.1U_0402_10V7K  [C_0402]  207.74 99.87 270 top
C1423  470P_0402_50V7K  [C_0402]  181.5 101.67 180 top
C1424  10U_0603_6.3V6M  [C_0603]  183.89 97.73 0 top
C1425  0.1U_0402_10V6K  [C_0402]  59.59 28.77 90 top
C1426  0.1U_0402_10V6K  [C_0402]  59.21 22.7 270 top
C1427  0.1U_0402_10V6K  [C_0402]  58.32 22.7 270 top
C1428  0.1U_0402_10V6K  [C_0402]  44.61 37.42 0 top
C1430  0.1U_0402_10V6K  [C_0402]  49.5 34.12 180 top
C1431  0.1U_0402_10V6K  [C_0402]  58.62 33.29 0 top
C1437  0.1U_0402_10V6K  [C_0402]  149.64 117.37 0 bottom
C1438  0.1U_0402_10V6K  [C_0402]  149.64 116.48 0 bottom
C1444  470P_0402_50V7K  [C_0402]  154.28 126.75 90 top
C1445  10U_0603_6.3V6M  [C_0603]  149 124.15 180 top
C1446  0.1U_0402_10V6K  [C_0402]  175.73 93.4 180 bottom
C1447  0.1U_0402_10V6K  [C_0402]  175.73 92.51 180 bottom
C1448  0.1U_0402_10V6K  [C_0402]  168.95 101.9 270 bottom
C1449  0.1U_0402_10V6K  [C_0402]  171.49 101.9 270 bottom
C1450  0.1U_0402_10V6K  [C_0402]  169.84 101.9 270 bottom
C1451  0.1U_0402_10V6K  [C_0402]  171.09 100.08 270 bottom
C1452  0.1U_0402_10V6K  [C_0402]  173.63 100.08 270 bottom
C1453  0.1U_0402_10V6K  [C_0402]  170.2 100.08 270 bottom
C1454  0.1U_0402_10V6K  [C_0402]  172.38 101.9 270 bottom
C1455  0.1U_0402_10V6K  [C_0402]  172.74 100.08 270 bottom
C1456  0.1U_0402_10V6K  [C_0402]  44.61 36.53 0 top
C1457  0.1U_0402_10V6K  [C_0402]  158.13 102.86 180 bottom
C1458  0.1U_0402_10V6K  [C_0402]  158.13 101.97 180 bottom
C1459  0.1U_0402_10V6K  [C_0402]  158.13 99.3 180 bottom
C1460  0.1U_0402_10V6K  [C_0402]  156.42 104.95 180 bottom
C1461  0.1U_0402_10V6K  [C_0402]  156.36 101.53 180 bottom
C1462  0.1U_0402_10V6K  [C_0402]  158.13 100.19 180 bottom
C1463  0.1U_0402_10V6K  [C_0402]  156.42 104.07 180 bottom
C1464  0.1U_0402_10V6K  [C_0402]  156.36 100.64 180 bottom
C1465  4700P_0402_25V7K  [C_0402]  204.96 110.8 270 top
C1466  27P_0402_50V8J  [C_0402]  188.33 122.58 180 bottom
C1467  100P_0402_50V8J  [C_0402]  113.45 140.62 270 bottom
C1468  100P_0402_50V8J  [C_0402]  112.5 140.62 270 bottom
C1469  4.7P_0402_50V8C  [C_0402]  207.57 133.24 180 bottom
C1470  1000P_0402_50V7K  [C_0402]  164.25 65.76 270 bottom
C1471  0.1U_0402_10V7K  [C_0402]  86.72 23.69 90 top
CC1  0.22U_0402_10V6K  [C_0402]  177.01 91.42 270 top
CC2  0.22U_0402_10V6K  [C_0402]  178.79 91.42 270 top
CC3  0.22U_0402_10V6K  [C_0402]  180.57 91.42 270 top
CC4  0.22U_0402_10V6K  [C_0402]  183.68 91.42 270 top
CC5  0.22U_0402_10V6K  [C_0402]  185.14 93.2 270 top
CC6  0.22U_0402_10V6K  [C_0402]  186.66 91.42 270 top
CC7  0.22U_0402_10V6K  [C_0402]  188.13 93.2 270 top
CC8  0.22U_0402_10V6K  [C_0402]  189.65 91.42 270 top
CC9  0.22U_0402_10V6K  [C_0402]  191.17 93.2 270 top
CC10  0.22U_0402_10V6K  [C_0402]  192.7 91.42 270 top
CC11  0.22U_0402_10V6K  [C_0402]  194.16 93.2 270 top
CC12  0.22U_0402_10V6K  [C_0402]  195.62 91.42 270 top
CC13  0.22U_0402_10V6K  [C_0402]  197.08 93.2 270 top
CC14  0.22U_0402_10V6K  [C_0402]  198.6 91.42 270 top
CC15  0.22U_0402_10V6K  [C_0402]  200.38 91.42 270 top
CC16  0.22U_0402_10V6K  [C_0402]  202.16 91.42 270 top
CC17  0.22U_0402_10V6K  [C_0402]  176.12 91.42 270 top
CC18  0.22U_0402_10V6K  [C_0402]  177.9 91.42 270 top
CC19  0.22U_0402_10V6K  [C_0402]  179.68 91.42 270 top
CC20  0.22U_0402_10V6K  [C_0402]  182.79 91.42 270 top
CC21  0.22U_0402_10V6K  [C_0402]  184.25 93.2 270 top
CC22  0.22U_0402_10V6K  [C_0402]  185.78 91.42 270 top
CC23  0.22U_0402_10V6K  [C_0402]  187.24 93.2 270 top
CC24  0.22U_0402_10V6K  [C_0402]  188.76 91.42 270 top
CC25  0.22U_0402_10V6K  [C_0402]  190.28 93.2 270 top
CC26  0.22U_0402_10V6K  [C_0402]  191.81 91.42 270 top
CC27  0.22U_0402_10V6K  [C_0402]  193.27 93.2 270 top
CC28  0.22U_0402_10V6K  [C_0402]  194.73 91.42 270 top
CC29  0.22U_0402_10V6K  [C_0402]  196.19 93.2 270 top
CC30  0.22U_0402_10V6K  [C_0402]  197.71 91.42 270 top
CC31  0.22U_0402_10V6K  [C_0402]  199.49 91.42 270 top
CC32  0.22U_0402_10V6K  [C_0402]  201.27 91.42 270 top
CC33  0.1U_0402_25V6  [C_0402]  153.3 14.94 0 top
CC35  0.1U_0402_25V6  [C_0402]  161.84 17.11 270 top
CC36  0.1U_0402_25V6  [C_0402]  151.33 16.28 0 top
CC37  0.1U_0402_25V6  [C_0402]  153.3 14.05 0 top
CC44  0.22U_0402_10V6K  [C_0402]  176.76 76.99 270 top
CC45  0.22U_0402_10V6K  [C_0402]  178.54 76.99 270 top
CC46  0.22U_0402_10V6K  [C_0402]  185.39 75.21 270 top
CC47  0.22U_0402_10V6K  [C_0402]  188.63 75.21 270 top
CC48  0.22U_0402_10V6K  [C_0402]  192.88 77.05 270 top
CC49  0.22U_0402_10V6K  [C_0402]  197.27 77.07 270 top
CC50  0.22U_0402_10V6K  [C_0402]  202.6 77.07 270 top
CC51  0.22U_0402_10V6K  [C_0402]  179.43 76.99 270 top
CC52  0.22U_0402_10V6K  [C_0402]  182.98 77.05 270 top
CC53  0.22U_0402_10V6K  [C_0402]  180.31 76.99 270 top
CC54  0.22U_0402_10V6K  [C_0402]  185.97 77.05 270 top
CC55  0.22U_0402_10V6K  [C_0402]  187.74 75.21 270 top
CC56  0.22U_0402_10V6K  [C_0402]  190.03 77.05 270 top
CC57  0.22U_0402_10V6K  [C_0402]  190.42 75.28 270 top
CC58  0.22U_0402_10V6K  [C_0402]  191.99 77.05 270 top
CC59  0.22U_0402_10V6K  [C_0402]  194.22 75.21 270 top
CC60  0.22U_0402_10V6K  [C_0402]  194.6 77.05 270 top
CC61  0.22U_0402_10V6K  [C_0402]  196.38 77.07 270 top
CC62  0.22U_0402_10V6K  [C_0402]  199.05 77.07 270 top
CC63  0.22U_0402_10V6K  [C_0402]  199.94 77.07 270 top
CC64  0.22U_0402_10V6K  [C_0402]  201.71 77.07 270 top
CC67  0.22U_0402_10V6K  [C_0402]  175.87 76.99 270 top
CC68  0.22U_0402_10V6K  [C_0402]  177.65 76.99 270 top
CC69  0.22U_0402_10V6K  [C_0402]  184.51 75.21 270 top
CC70  0.22U_0402_10V6K  [C_0402]  189.14 77.05 270 top
CC71  0.22U_0402_10V6K  [C_0402]  193.33 75.21 270 top
CC72  0.22U_0402_10V6K  [C_0402]  198.16 77.07 270 top
CC73  0.22U_0402_10V6K  [C_0402]  183.87 77.05 270 top
CC74  0.22U_0402_10V6K  [C_0402]  186.86 77.05 270 top
CC75  0.22U_0402_10V6K  [C_0402]  191.3 75.28 270 top
CC76  0.22U_0402_10V6K  [C_0402]  195.49 77.05 270 top
CC77  0.22U_0402_10V6K  [C_0402]  200.83 77.07 270 top
CC81  22U_0603_6.3V6M  [C_0603]  163.43 51.52 0 bottom
CC82  22U_0603_6.3V6M  [C_0603]  163.43 56.34 0 bottom
CC83  22U_0603_6.3V6M  [C_0603]  163.43 31.77 0 bottom
CC84  22U_0603_6.3V6M  [C_0603]  163.49 44.41 0 bottom
CC161  10U_0603_6.3V6M  [C_0603]  163.43 55.07 0 bottom
CC163  10U_0603_6.3V6M  [C_0603]  163.49 40.22 0 bottom
CC164  10U_0603_6.3V6M  [C_0603]  163.43 28.98 0 bottom
CC165  10U_0603_6.3V6M  [C_0603]  163.43 27.71 0 bottom
CC166  10U_0603_6.3V6M  [C_0603]  163.43 34.82 0 bottom
CC167  10U_0603_6.3V6M  [C_0603]  163.43 50.25 0 bottom
CC168  10U_0603_6.3V6M  [C_0603]  163.49 43.14 0 bottom
CC169  10U_0603_6.3V6M  [C_0603]  178.95 16.14 180 top
CC170  10U_0603_6.3V6M  [C_0603]  163.49 38.95 0 bottom
CC171  10U_0603_6.3V6M  [C_0603]  163.43 30.5 0 bottom
CC172  10U_0603_6.3V6M  [C_0603]  163.43 36.09 0 bottom
CC173  10U_0603_6.3V6M  [C_0603]  178.95 14.87 180 top
CC174  10U_0603_6.3V6M  [C_0603]  178.95 13.67 180 top
CC175  10U_0603_6.3V6M  [C_0603]  185.75 18.27 270 bottom
CC176  10U_0603_6.3V6M  [C_0603]  184.48 18.27 270 bottom
CC177  10U_0603_6.3V6M  [C_0603]  182.89 18.27 270 bottom
CC178  10U_0603_6.3V6M  [C_0603]  181.75 16.93 180 bottom
CC179  10U_0603_6.3V6M  [C_0603]  181.75 18.14 180 bottom
CC180  10U_0603_6.3V6M  [C_0603]  185.4 14.5 90 bottom
CC181  10U_0603_6.3V6M  [C_0603]  184.13 14.5 90 bottom
CC182  10U_0603_6.3V6M  [C_0603]  181.62 15.73 0 bottom
CC183  10U_0603_6.3V6M  [C_0603]  179.91 15.73 180 bottom
CC184  10U_0603_6.3V6M  [C_0603]  179.91 14.52 180 bottom
CC185  10U_0603_6.3V6M  [C_0603]  165.29 52.98 270 top
CC186  1U_0402_6.3V6K  [C_0402]  219.03 72.2 90 top
CC187  22U_0603_6.3V6M  [C_0603]  195.75 72.47 180 bottom
CC188  22U_0603_6.3V6M  [C_0603]  195.75 71.27 180 bottom
CC189  22U_0603_6.3V6M  [C_0603]  195.62 70.06 180 bottom
CC190  10U_0603_6.3V6M  [C_0603]  181.17 12.01 90 top
CC191  1U_0402_6.3V6K  [C_0402]  191.05 68.09 0 bottom
